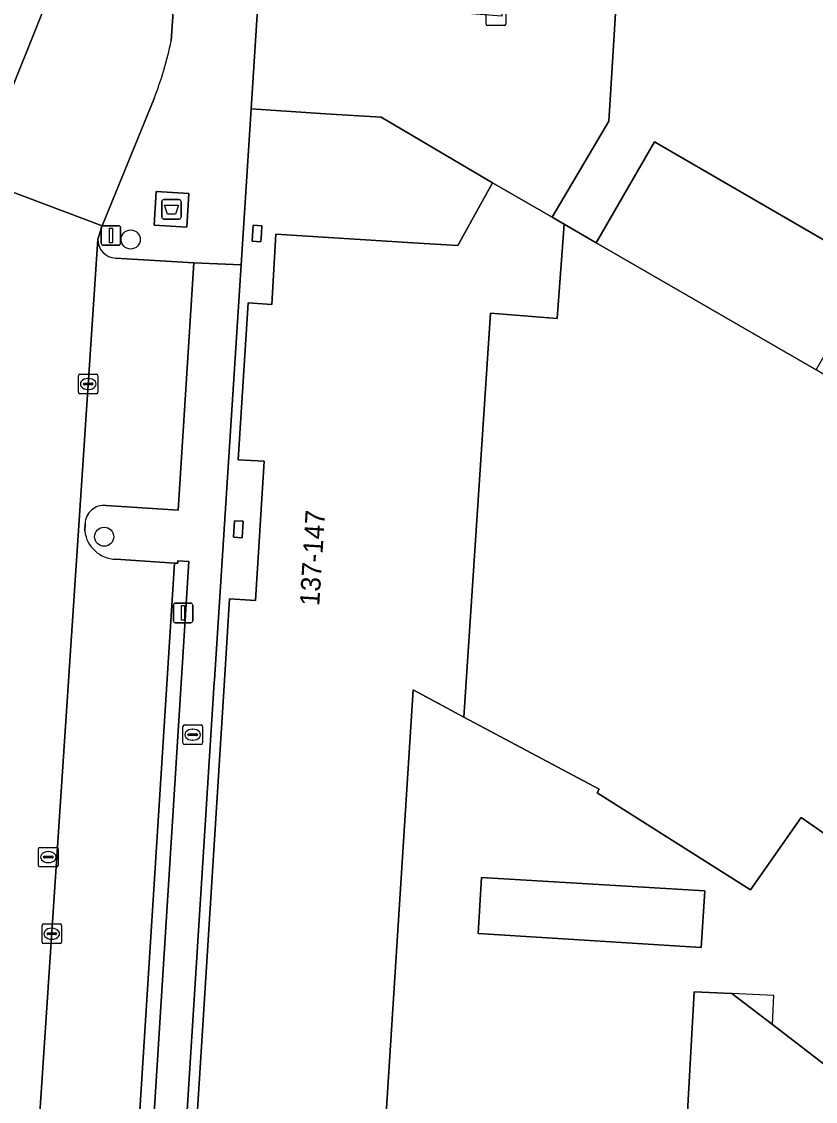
# Model space of a CAD drawing. Extents: x 160102 to 160934, y 382045 to 382923.
# Drawn here: x 160547.1 to 160587.8, y 382351.5 to 382406.8 of the extents above; entities that cross this region are included whole.
import ezdxf

# ---------------------------------------------------------------- set-up
doc = ezdxf.new("R2010")
doc.units = 0
for name, color, linetype in [('IMGEO_Afval_apart_plaats', 7, 'Continuous'), ('IMGEO_Boom', 7, 'Continuous'), ('IMGEO_Brandkraan', 7, 'Continuous'), ('IMGEO_Erf', 7, 'Continuous'), ('IMGEO_Groenvoorziening', 7, 'Continuous'), ('IMGEO_Haag', 7, 'Continuous'), ('IMGEO_Kolk', 7, 'Continuous'), ('IMGEO_Lichtmast', 7, 'Continuous'), ('IMGEO_Pand', 7, 'Continuous'), ('IMGEO_Pand_nummerreeks', 7, 'Continuous'), ('IMGEO_Pand_overbouw', 7, 'Continuous'), ('IMGEO_Parkeervlak_open', 7, 'Continuous'), ('IMGEO_Rijbaan_lokaal_open', 7, 'Continuous'), ('IMGEO_Rioolput', 7, 'Continuous'), ('IMGEO_Voetpad_gesloten', 7, 'Continuous'), ('IMGEO_Voetpad_open', 7, 'Continuous')]:
    doc.layers.add(name, color=color, linetype=linetype)

msp = doc.modelspace()

# ---------------------------------------------------------------- linework, layer by layer
at = {"layer": 'IMGEO_Afval_apart_plaats'}
for p, q in [((160554.315, 382396.807), (160554.315, 382397.607)), ((160554.315, 382397.607), (160554.315, 382396.807)), ((160554.415, 382397.707), (160555.205, 382397.707)), ((160555.205, 382397.707), (160554.415, 382397.707)), ((160555.305, 382397.607), (160555.305, 382396.807)), ((160555.305, 382396.807), (160555.305, 382397.607)), ((160555.205, 382396.707), (160554.415, 382396.707)), ((160554.415, 382396.707), (160555.205, 382396.707))]:
    msp.add_line(p, q, dxfattribs=at)
msp.add_lwpolyline([(160554.458, 382397.421), (160555.162, 382397.421), (160555.013, 382396.951), (160554.607, 382396.951), (160554.458, 382397.421)], dxfattribs=at)
for centre, start, end in [((160554.415, 382397.607), 90, 180), ((160554.415, 382397.607), 90, 180), ((160555.205, 382397.607), 0, 90), ((160555.205, 382397.607), 360, 90), ((160554.415, 382396.807), 180, 270), ((160554.415, 382396.807), 180, 270), ((160555.205, 382396.807), 270, 0), ((160555.205, 382396.807), 270, 0)]:
    msp.add_arc(centre, 0.1, start, end, dxfattribs=at)
at = {"layer": 'IMGEO_Boom'}
for centre in [(160552.72, 382395.659), (160551.364, 382380.439)]:
    msp.add_circle(centre, 0.489, dxfattribs=at)
at = {"layer": 'IMGEO_Brandkraan'}
for p, q in [((160555.396, 382369.872), (160555.396, 382370.724)), ((160555.471, 382370.798), (160556.323, 382370.798)), ((160555.884, 382370.578), (160555.909, 382370.578)), ((160556.397, 382370.724), (160556.397, 382369.872)), ((160555.655, 382370.292), (160555.655, 382370.304)), ((160556.093, 382370.255), (160555.695, 382370.255)), ((160555.698, 382370.341), (160556.096, 382370.341)), ((160555.907, 382370.018), (160555.882, 382370.018)), ((160556.139, 382370.304), (160556.139, 382370.292)), ((160556.323, 382369.798), (160555.471, 382369.798))]:
    msp.add_line(p, q, dxfattribs=at)
for points in [[(160555.396, 382369.872), (160555.396, 382370.724)], [(160555.471, 382370.798), (160556.323, 382370.798)], [(160556.397, 382370.724), (160556.397, 382369.872)], [(160556.323, 382369.798), (160555.471, 382369.798)]]:
    msp.add_lwpolyline(points, dxfattribs=at)
for centre, radius, start, end in [((160555.473, 382370.722), 0.0765, 91.552, 178.448), ((160555.473, 382370.722), 0.0765, 91.552, 178.448), ((160556.321, 382370.722), 0.0765, 1.552, 88.448), ((160556.321, 382370.722), 0.0765, 1.552, 88.448), ((160555.473, 382369.874), 0.0765, 181.552, 268.448), ((160555.473, 382369.874), 0.0765, 181.552, 268.448), ((160555.695, 382370.301), 0.0403, 85.8775, 175.7526), ((160555.692, 382370.291), 0.0366, 178.938, 274.7102), ((160556.096, 382370.298), 0.043, 264.8664, 352.4533), ((160556.1, 382370.303), 0.0386, 1.7309, 96.639), ((160556.321, 382369.874), 0.0765, 271.552, 358.448), ((160556.321, 382369.874), 0.0765, 271.552, 358.448)]:
    msp.add_arc(centre, radius, start, end, dxfattribs=at)
for centre, major_axis, ratio, start_param, end_param in [((160555.883, 382370.298), (-0.387, 0.002), 0.722429, 4.712389, 7.853982), ((160555.908, 382370.298), (-0.39, 0.002), 0.717154, 1.570796, 4.712389)]:
    msp.add_ellipse(centre, major_axis=major_axis, ratio=ratio, start_param=start_param, end_param=end_param, dxfattribs=at)
at = {"layer": 'IMGEO_Erf'}
for points in [[(160580.077, 382448.126), (160577.211, 382401.721), (160574.304, 382396.803), (160574.922, 382396.446), (160576.566, 382395.495), (160579.551, 382400.655), (160590.805, 382394.145)], [(160600.944, 382356.385), (160587.063, 382366.06), (160584.473, 382362.344), (160576.608, 382367.311), (160576.716, 382367.513), (160569.791, 382371.203), (160567.185, 382372.592), (160565.316, 382343.121), (160556.788, 382343.667), (160556.703, 382342.293), (160569.194, 382341.52), (160569.6, 382348.084), (160571.897, 382347.942), (160571.49, 382341.378), (160580.676, 382340.81), (160581.575, 382357.12), (160583.507, 382357.047), (160585.586, 382355.449), (160593.688, 382349.22)]]:
    msp.add_lwpolyline(points, dxfattribs=at)
for points in [[(160557.522, 382373.07), (160557.785, 382377.251), (160559.108, 382377.167), (160559.555, 382384.3), (160558.231, 382384.379), (160558.741, 382392.414), (160559.948, 382392.338), (160560.155, 382395.931), (160567.173, 382395.492), (160569.484, 382395.348), (160571.251, 382398.569), (160565.545, 382401.922), (160562.694, 382402.095), (160558.887, 382402.35), (160558.375, 382394.367), (160557.011, 382373.102), (160557.003, 382372.972), (160555.149, 382343.743), (160555.68, 382343.738)], [(160558.934, 382395.576), (160558.993, 382396.396), (160559.442, 382396.363), (160559.414, 382395.978), (160559.382, 382395.548)], [(160557.987, 382380.406), (160558.044, 382381.254), (160558.486, 382381.226), (160558.433, 382380.378)], [(160570.51, 382360.111), (160570.688, 382362.99), (160582.118, 382362.301), (160581.934, 382359.406)]]:
    msp.add_lwpolyline(points, close=True, dxfattribs=at)
at = {"layer": 'IMGEO_Groenvoorziening'}
msp.add_lwpolyline([(160555.705, 382379.174), (160555.127, 382379.209), (160555.14, 382379.077), (160554.966, 382379.08), (160552.798, 382344.863), (160552.617, 382342.003), (160553.366, 382341.959)], close=True, dxfattribs=at)
at = {"layer": 'IMGEO_Haag'}
msp.add_lwpolyline([(160555.705, 382379.174), (160555.127, 382379.209), (160555.14, 382379.077), (160554.966, 382379.08), (160552.798, 382344.863), (160552.617, 382342.003), (160553.366, 382341.959)], close=True, dxfattribs=at)
at = {"layer": 'IMGEO_Kolk'}
for p, q in [((160570.926, 382406.695), (160570.926, 382407.547)), ((160571.927, 382407.547), (160571.927, 382406.695)), ((160571.853, 382406.621), (160571.001, 382406.621)), ((160550.044, 382387.834), (160550.044, 382388.686)), ((160550.119, 382388.76), (160550.971, 382388.76)), ((160551.045, 382388.686), (160551.045, 382387.834)), ((160550.303, 382388.254), (160550.303, 382388.266)), ((160550.741, 382388.217), (160550.343, 382388.217)), ((160550.346, 382388.303), (160550.744, 382388.303)), ((160550.532, 382388.54), (160550.557, 382388.54)), ((160550.787, 382388.266), (160550.787, 382388.254)), ((160550.971, 382387.76), (160550.119, 382387.76)), ((160550.555, 382387.98), (160550.53, 382387.98)), ((160548.18, 382359.676), (160548.18, 382360.528)), ((160548.255, 382360.602), (160549.107, 382360.602)), ((160549.181, 382360.528), (160549.181, 382359.676)), ((160548.439, 382360.096), (160548.439, 382360.108)), ((160548.877, 382360.059), (160548.479, 382360.059)), ((160548.482, 382360.145), (160548.88, 382360.145)), ((160548.668, 382360.382), (160548.693, 382360.382)), ((160548.923, 382360.108), (160548.923, 382360.096)), ((160549.107, 382359.602), (160548.255, 382359.602)), ((160548.691, 382359.822), (160548.666, 382359.822))]:
    msp.add_line(p, q, dxfattribs=at)
for points in [[(160570.926, 382406.695), (160570.926, 382407.547)], [(160571.927, 382407.547), (160571.927, 382406.695)], [(160571.853, 382406.621), (160571.001, 382406.621)], [(160550.044, 382387.834), (160550.044, 382388.686)], [(160550.119, 382388.76), (160550.971, 382388.76)], [(160551.045, 382388.686), (160551.045, 382387.834)], [(160550.971, 382387.76), (160550.119, 382387.76)], [(160548.18, 382359.676), (160548.18, 382360.528)], [(160548.255, 382360.602), (160549.107, 382360.602)], [(160549.181, 382360.528), (160549.181, 382359.676)], [(160549.107, 382359.602), (160548.255, 382359.602)]]:
    msp.add_lwpolyline(points, dxfattribs=at)
for centre, radius, start, end in [((160571.003, 382406.697), 0.0765, 181.552, 268.448), ((160571.003, 382406.697), 0.0765, 181.552, 268.448), ((160571.851, 382406.697), 0.0765, 271.552, 358.448), ((160571.851, 382406.697), 0.0765, 271.552, 358.448), ((160550.121, 382388.684), 0.0765, 91.552, 178.448), ((160550.121, 382388.684), 0.0765, 91.552, 178.448), ((160550.969, 382388.684), 0.0765, 1.552, 88.448), ((160550.969, 382388.684), 0.0765, 1.552, 88.448), ((160550.343, 382388.263), 0.0403, 85.8775, 175.7526), ((160550.34, 382388.253), 0.0366, 178.938, 274.7102), ((160550.744, 382388.26), 0.043, 264.8664, 352.4533), ((160550.748, 382388.265), 0.0386, 1.7309, 96.639), ((160550.121, 382387.836), 0.0765, 181.552, 268.448), ((160550.121, 382387.836), 0.0765, 181.552, 268.448), ((160550.969, 382387.836), 0.0765, 271.552, 358.448), ((160550.969, 382387.836), 0.0765, 271.552, 358.448), ((160548.257, 382360.526), 0.0765, 91.552, 178.448), ((160548.257, 382360.526), 0.0765, 91.552, 178.448), ((160549.105, 382360.526), 0.0765, 1.552, 88.448), ((160549.105, 382360.526), 0.0765, 1.552, 88.448), ((160548.479, 382360.105), 0.0403, 85.8775, 175.7526), ((160548.476, 382360.095), 0.0366, 178.938, 274.7102), ((160548.88, 382360.102), 0.043, 264.8664, 352.4533), ((160548.884, 382360.107), 0.0386, 1.7309, 96.639), ((160548.257, 382359.678), 0.0765, 181.552, 268.448), ((160548.257, 382359.678), 0.0765, 181.552, 268.448), ((160549.105, 382359.678), 0.0765, 271.552, 358.448), ((160549.105, 382359.678), 0.0765, 271.552, 358.448)]:
    msp.add_arc(centre, radius, start, end, dxfattribs=at)
for centre, major_axis, ratio, start_param, end_param in [((160550.531, 382388.26), (-0.387, 0.002), 0.722429, 4.712389, 7.853982), ((160550.556, 382388.26), (-0.39, 0.002), 0.717154, 1.570796, 4.712389), ((160548.667, 382360.102), (-0.387, 0.002), 0.722429, 4.712389, 7.853982), ((160548.692, 382360.102), (-0.39, 0.002), 0.717154, 1.570796, 4.712389)]:
    msp.add_ellipse(centre, major_axis=major_axis, ratio=ratio, start_param=start_param, end_param=end_param, dxfattribs=at)
at = {"layer": 'IMGEO_Lichtmast'}
for p, q in [((160551.311, 382396.367), (160552.101, 382396.367)), ((160552.101, 382396.367), (160551.311, 382396.367)), ((160551.211, 382395.467), (160551.211, 382396.267)), ((160551.211, 382396.267), (160551.211, 382395.467)), ((160552.201, 382396.267), (160552.201, 382395.467)), ((160552.201, 382395.467), (160552.201, 382396.267)), ((160552.101, 382395.367), (160551.311, 382395.367)), ((160551.311, 382395.367), (160552.101, 382395.367)), ((160555.006, 382377.035), (160555.796, 382377.035)), ((160555.796, 382377.035), (160555.006, 382377.035)), ((160554.906, 382376.135), (160554.906, 382376.935)), ((160554.906, 382376.935), (160554.906, 382376.135)), ((160555.896, 382376.935), (160555.896, 382376.135)), ((160555.896, 382376.135), (160555.896, 382376.935)), ((160555.796, 382376.035), (160555.006, 382376.035)), ((160555.006, 382376.035), (160555.796, 382376.035))]:
    msp.add_line(p, q, dxfattribs=at)
for points in [[(160551.631, 382396.242), (160551.781, 382396.242), (160551.781, 382395.492), (160551.631, 382395.492), (160551.631, 382396.242)], [(160555.326, 382376.91), (160555.476, 382376.91), (160555.476, 382376.16), (160555.326, 382376.16), (160555.326, 382376.91)]]:
    msp.add_lwpolyline(points, dxfattribs=at)
for centre, start, end in [((160551.311, 382396.267), 90, 180), ((160551.311, 382396.267), 90, 180), ((160552.101, 382396.267), 0, 90), ((160552.101, 382396.267), 360, 90), ((160551.311, 382395.467), 180, 270), ((160551.311, 382395.467), 180, 270), ((160552.101, 382395.467), 270, 0), ((160552.101, 382395.467), 270, 0), ((160555.006, 382376.935), 90, 180), ((160555.006, 382376.935), 90, 180), ((160555.796, 382376.935), 0, 90), ((160555.796, 382376.935), 360, 90), ((160555.006, 382376.135), 180, 270), ((160555.006, 382376.135), 180, 270), ((160555.796, 382376.135), 270, 0), ((160555.796, 382376.135), 270, 0)]:
    msp.add_arc(centre, 0.1, start, end, dxfattribs=at)
at = {"layer": 'IMGEO_Pand'}
for points in [[(160590.805, 382394.145), (160579.551, 382400.655), (160576.566, 382395.495), (160587.82, 382388.985)], [(160567.185, 382372.592), (160569.791, 382371.203), (160571.142, 382391.888), (160574.571, 382391.606), (160574.922, 382396.446), (160574.304, 382396.803), (160571.251, 382398.569), (160569.484, 382395.348), (160567.173, 382395.492), (160560.155, 382395.931), (160559.948, 382392.338), (160558.741, 382392.414), (160558.231, 382384.379), (160559.555, 382384.3), (160559.108, 382377.167), (160557.785, 382377.251), (160557.522, 382373.07), (160555.68, 382343.738), (160556.788, 382343.667), (160565.316, 382343.121)], [(160559.414, 382395.978), (160559.442, 382396.363), (160558.993, 382396.396), (160558.934, 382395.576), (160559.382, 382395.548)], [(160601.579, 382380.565), (160587.82, 382388.985), (160576.566, 382395.495), (160574.922, 382396.446), (160574.571, 382391.606), (160571.142, 382391.888), (160569.791, 382371.203), (160576.716, 382367.513), (160576.608, 382367.311), (160584.473, 382362.344), (160587.063, 382366.06), (160600.944, 382356.385), (160607.426, 382365.685), (160613.933, 382373.305), (160614.005, 382373.39), (160613.777, 382373.634)], [(160558.486, 382381.226), (160558.044, 382381.254), (160557.987, 382380.406), (160558.433, 382380.378)], [(160581.934, 382359.406), (160582.118, 382362.301), (160570.688, 382362.99), (160570.51, 382360.111)]]:
    msp.add_lwpolyline(points, close=True, dxfattribs=at)
msp.add_lwpolyline([(160587.757, 382339.068), (160585.979, 382340.453), (160586.26, 382345.268), (160586.342, 382346.677), (160591.48, 382346.353), (160593.688, 382349.22), (160585.586, 382355.449), (160583.507, 382357.047), (160581.575, 382357.12), (160580.676, 382340.81), (160571.49, 382341.378), (160571.897, 382347.942), (160569.6, 382348.084), (160569.194, 382341.52), (160556.703, 382342.293), (160556.108, 382332.729), (160559.732, 382332.515), (160575.46, 382331.588)], dxfattribs=at)
at = {"layer": 'IMGEO_Pand_overbouw'}
msp.add_lwpolyline([(160585.586, 382355.449), (160585.664, 382356.936), (160583.507, 382357.047)], close=True, dxfattribs=at)
at = {"layer": 'IMGEO_Parkeervlak_open'}
for points in [[(160551.035, 382395.683), (160547.289, 382339.093), (160547.716, 382339.069), (160547.775, 382340.016), (160547.892, 382341.885)], [(160551.458, 382382.04), (160555.145, 382381.8), (160555.957, 382394.46), (160551.941, 382394.7)], [(160550.369, 382380.731), (160550.387, 382381.096)], [(160554.966, 382379.08), (160551.957, 382379.282)], [(160548.354, 382342.256), (160552.617, 382342.003), (160552.798, 382344.863), (160554.966, 382379.08)]]:
    msp.add_lwpolyline(points, dxfattribs=at)
for centre, radius, start, end in [((160552.003, 382395.666), 0.968, 178.9895, 266.3421), ((160551.368, 382381.063), 0.982, 84.7351, 178.052), ((160552.007, 382380.931), 1.65, 186.9658, 268.2752)]:
    msp.add_arc(centre, radius, start, end, dxfattribs=at)
at = {"layer": 'IMGEO_Rijbaan_lokaal_open'}
msp.add_lwpolyline([(160580.077, 382448.126), (160574.329, 382448.711), (160573.941, 382443.836), (160573.589, 382438.835), (160573.238, 382433.856), (160571.729, 382407.102), (160563.732, 382407.708), (160559.249, 382407.996), (160558.887, 382402.35), (160562.694, 382402.095), (160565.545, 382401.922), (160571.251, 382398.569), (160574.304, 382396.803), (160577.211, 382401.721)], close=True, dxfattribs=at)
for points in [[(160554.791, 382405.833), (160555.279, 382412.858), (160550.307, 382413.134), (160550.046, 382412.148), (160549.757, 382411.194), (160546.416, 382402.829)], [(160545.261, 382398.617), (160551.259, 382396.364), (160553.917, 382402.888)], [(160551.035, 382395.683), (160551.259, 382396.364), (160545.261, 382398.617), (160545.22, 382397.985)], [(160542.87, 382357.448), (160541.478, 382339.999), (160541.437, 382339.428), (160547.289, 382339.093), (160551.035, 382395.683)]]:
    msp.add_lwpolyline(points, dxfattribs=at)
msp.add_arc((160538.465, 382409.076), 16.645, 338.1756, 348.7653, dxfattribs=at)
at = {"layer": 'IMGEO_Rioolput'}
for p, q in [((160548.002, 382363.601), (160548.002, 382364.453)), ((160548.077, 382364.527), (160548.929, 382364.527)), ((160548.49, 382364.307), (160548.515, 382364.307)), ((160549.003, 382364.453), (160549.003, 382363.601)), ((160548.261, 382364.021), (160548.261, 382364.033)), ((160548.699, 382363.984), (160548.301, 382363.984)), ((160548.304, 382364.07), (160548.702, 382364.07)), ((160548.513, 382363.747), (160548.488, 382363.747)), ((160548.745, 382364.033), (160548.745, 382364.021)), ((160548.929, 382363.527), (160548.077, 382363.527))]:
    msp.add_line(p, q, dxfattribs=at)
for points in [[(160548.002, 382363.601), (160548.002, 382364.453)], [(160548.077, 382364.527), (160548.929, 382364.527)], [(160549.003, 382364.453), (160549.003, 382363.601)], [(160548.929, 382363.527), (160548.077, 382363.527)]]:
    msp.add_lwpolyline(points, dxfattribs=at)
for centre, radius, start, end in [((160548.079, 382364.451), 0.0765, 91.552, 178.448), ((160548.079, 382364.451), 0.0765, 91.552, 178.448), ((160548.927, 382364.451), 0.0765, 1.552, 88.448), ((160548.927, 382364.451), 0.0765, 1.552, 88.448), ((160548.301, 382364.03), 0.0403, 85.8775, 175.7526), ((160548.298, 382364.02), 0.0366, 178.938, 274.7102), ((160548.702, 382364.027), 0.043, 264.8664, 352.4533), ((160548.706, 382364.032), 0.0386, 1.7309, 96.639), ((160548.079, 382363.603), 0.0765, 181.552, 268.448), ((160548.079, 382363.603), 0.0765, 181.552, 268.448), ((160548.927, 382363.603), 0.0765, 271.552, 358.448), ((160548.927, 382363.603), 0.0765, 271.552, 358.448)]:
    msp.add_arc(centre, radius, start, end, dxfattribs=at)
for centre, major_axis, ratio, start_param, end_param in [((160548.489, 382364.027), (-0.387, 0.002), 0.722429, 4.712389, 7.853982), ((160548.514, 382364.027), (-0.39, 0.002), 0.717154, 1.570796, 4.712389)]:
    msp.add_ellipse(centre, major_axis=major_axis, ratio=ratio, start_param=start_param, end_param=end_param, dxfattribs=at)
at = {"layer": 'IMGEO_Voetpad_gesloten'}
msp.add_lwpolyline([(160555.7, 382398.016), (160554.021, 382398.115), (160553.92, 382396.397), (160555.599, 382396.298)], close=True, dxfattribs=at)
at = {"layer": 'IMGEO_Voetpad_open'}
for points in [[(160558.887, 382402.35), (160559.249, 382407.996), (160558.716, 382408.042), (160562.832, 382471.504), (160563.138, 382478.974), (160564.171, 382478.904), (160564.791, 382489.095), (160565.01, 382492.688), (160565.455, 382500), (160565.683, 382503.748), (160561.879, 382503.99), (160561.16, 382503.138), (160561.099, 382502.496), (160563.447, 382502.388), (160563.299, 382500), (160562.008, 382479.189), (160560.589, 382479.258), (160560.13, 382472.203), (160559.092, 382472.271), (160559.093, 382471.97)], [(160546.416, 382402.829), (160549.757, 382411.194), (160550.046, 382412.148), (160550.307, 382413.134)], [(160555.279, 382412.858), (160554.791, 382405.833)], [(160553.917, 382402.888), (160551.259, 382396.364), (160551.035, 382395.683)], [(160551.941, 382394.7), (160555.957, 382394.46), (160558.375, 382394.367), (160558.887, 382402.35)], [(160558.375, 382394.367), (160555.957, 382394.46), (160555.145, 382381.8), (160551.458, 382382.04)], [(160559.96, 382294.804), (160557.4, 382297.821), (160553.732, 382298.045), (160554.302, 382306.831), (160554.554, 382310.417), (160556.032, 382332.735), (160555.474, 382332.78), (160556.093, 382342.324), (160556.703, 382342.293), (160556.788, 382343.667), (160555.68, 382343.738), (160555.149, 382343.743), (160557.003, 382372.972), (160557.011, 382373.102), (160558.375, 382394.367)], [(160550.387, 382381.096), (160550.369, 382380.731)], [(160551.957, 382379.282), (160554.966, 382379.08), (160555.14, 382379.077), (160555.127, 382379.209), (160555.705, 382379.174), (160553.366, 382341.959), (160552.617, 382342.003), (160548.354, 382342.256)]]:
    msp.add_lwpolyline(points, dxfattribs=at)
msp.add_lwpolyline([(160555.7, 382398.016), (160555.599, 382396.298), (160553.92, 382396.397), (160554.021, 382398.115)], close=True, dxfattribs=at)
for centre, radius, start, end in [((160538.465, 382409.076), 16.645, 338.1756, 348.7653), ((160552.003, 382395.666), 0.968, 178.9895, 266.3421), ((160551.368, 382381.063), 0.982, 84.7351, 178.052), ((160552.007, 382380.931), 1.65, 186.9658, 268.2752)]:
    msp.add_arc(centre, radius, start, end, dxfattribs=at)

# ---------------------------------------------------------------- texts
at = {"layer": 'IMGEO_Pand_nummerreeks'}
msp.add_text('137-147', height=1, rotation=86.4135, dxfattribs=at).set_placement((160562.376, 382376.869))

doc.saveas('drawing.dxf')
